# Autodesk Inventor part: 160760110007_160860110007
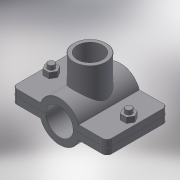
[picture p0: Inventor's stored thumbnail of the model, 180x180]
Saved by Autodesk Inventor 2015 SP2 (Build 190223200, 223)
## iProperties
Created: 2017-05
Part Number: 160760110007_160860110007
Material: Generic
Description: PLASSON SADDLE 110-3/4"
Document SubType Name: Modeling
Designer: KIM
Density: 1 g/cm^3
Appearance: Default
Author: KIM
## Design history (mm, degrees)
derived "16076.ipt"
feature "Solid1::16076.ipt"
feature "Solid2::16076.ipt"
tag "TaggingFeature1"
body "Solid1"
other parameters: "d0" = 121, "d1" = 165, "d2" = 55, "d4" = 116, "d5" = 0, "d6" = 8.25, "d7" = 165, "d8" = 0.1, "d10" = 0, "d11" = 1.1, "d14" = 31.3521, "d20" = 1.1, "d23" = 1.1, "d36" = 13, "d37" = 10.4, "d38" = 63, "d39" = 0, "d40" = 3, "d41" = 5, "d42" = 0, "d43" = 8, "d44" = 3, "d45" = 0, "d46" = 1.1, "d51" = 84, "d52" = 24.117, "d53" = 19, "d54" = 0, "d57" = 0, "d58" = 118.8, "d60" = 0, "d62" = 13, "d63" = 10.4, "d66" = 95.2, "G_" = 24.117, "A_" = 84, "L_" = 165, "L_1" = 116, "l_2" = 19
